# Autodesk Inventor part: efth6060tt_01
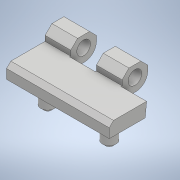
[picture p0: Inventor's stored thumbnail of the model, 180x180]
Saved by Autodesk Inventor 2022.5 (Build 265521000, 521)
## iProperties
Part Number: efth6060tt_01
Material: 一般
Document SubType Name: Modeling
Designer: ImaoCorp
Density: 1 g/cm^3
Appearance: 既定
Author: ImaoCorp
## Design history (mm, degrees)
feature "efth6060tt_01"
node "ソリッド1"
